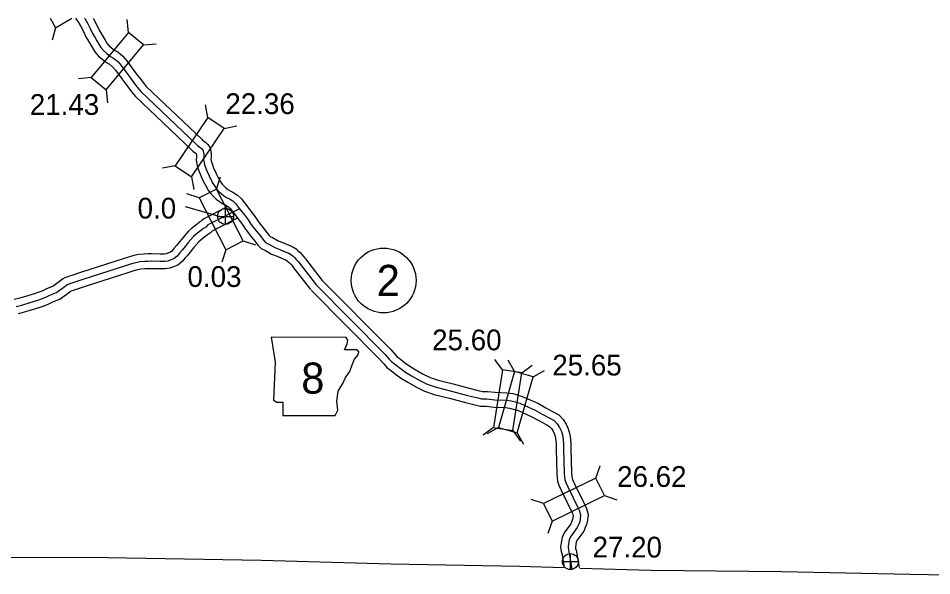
# Model space of a CAD drawing. Extents: x -83719 to 153526, y -11835 to 11446.
# Drawn here: x -4375 to -3756, y -4528 to -4150 of the extents above; entities that cross this region are included whole.
import ezdxf

# ---------------------------------------------------------------- set-up
doc = ezdxf.new("R2010")
doc.units = 0
for name, color, linetype in [('Level 10', 7, 'Continuous'), ('Level 2', 7, 'Continuous'), ('Level 20', 7, 'Continuous'), ('Level 21', 7, 'Continuous'), ('Level 25', 7, 'Continuous'), ('Level 26', 7, 'Continuous'), ('Level 27', 7, 'Continuous'), ('Level 58', 7, 'Continuous'), ('Level 59', 7, 'Continuous')]:
    doc.layers.add(name, color=color, linetype=linetype)

msp = doc.modelspace()

# ---------------------------------------------------------------- linework, layer by layer
at = {"layer": 'Level 10'}
for points in [[(-4336.57, -4149.53), (-4336.12, -4150.18), (-4334.58, -4152.45), (-4332.93, -4155.2), (-4331.25, -4158.56), (-4329.54, -4162.18), (-4327.88, -4164.97), (-4326.44, -4167.34), (-4325.07, -4169.56), (-4323.57, -4172.21), (-4321.25, -4174.97), (-4318.65, -4177.26), (-4315.71, -4179.58), (-4313.68, -4180.7), (-4311.48, -4182.52), (-4309.5, -4184.75), (-4305.1, -4190.67), (-4303.27, -4193.34), (-4301.01, -4196.33), (-4298.6, -4199.4), (-4295.95, -4202.63), (-4258.08, -4238.6), (-4257.12, -4239.64), (-4255.52, -4240.84), (-4254.71, -4241.39), (-4254.7, -4241.41), (-4254.66, -4241.56), (-4254.61, -4242.01), (-4254.63, -4243.43), (-4254.73, -4245.9), (-4254.29, -4248.37), (-4253.83, -4250.22), (-4252.94, -4253.02), (-4251.87, -4255.69), (-4250.82, -4257.92), (-4249.93, -4259.95), (-4249.1, -4261.54), (-4248.17, -4263.29), (-4246.57, -4266.09), (-4244.77, -4268.42), (-4242.85, -4270.66), (-4241.09, -4272.35), (-4239.02, -4273.8), (-4236.74, -4275.38), (-4234.66, -4276.39), (-4232.92, -4277.48), (-4231.72, -4278.6), (-4229.2, -4281.83)], [(-4324.67, -4149.53), (-4324.16, -4150.37), (-4322.25, -4154.2), (-4320.7, -4157.49), (-4319.31, -4159.82), (-4317.92, -4162.11), (-4316.46, -4164.47), (-4315.32, -4166.48), (-4314.07, -4167.96), (-4312.24, -4169.58), (-4310.15, -4171.23), (-4308.03, -4172.4), (-4304.52, -4175.29), (-4301.73, -4178.43), (-4296.96, -4184.86), (-4295.15, -4187.5), (-4293.1, -4190.22), (-4290.8, -4193.13), (-4288.61, -4195.8), (-4250.98, -4231.56), (-4250.4, -4232.18), (-4249.71, -4232.7), (-4248.21, -4233.71), (-4246.88, -4235.09), (-4246.18, -4236.16), (-4245.36, -4237.57), (-4244.78, -4239.81), (-4244.61, -4241.57), (-4244.63, -4243.69), (-4244.7, -4245.23), (-4244.51, -4246.29), (-4244.21, -4247.5), (-4243.53, -4249.63), (-4242.7, -4251.69), (-4241.71, -4253.78), (-4240.91, -4255.62), (-4240.24, -4256.89), (-4239.41, -4258.47), (-4238.24, -4260.52), (-4237.02, -4262.1), (-4235.57, -4263.78), (-4234.71, -4264.6), (-4233.29, -4265.6), (-4231.68, -4266.72), (-4229.82, -4267.62), (-4226.8, -4269.5), (-4224.31, -4271.83), (-4221.31, -4275.69)], [(-4233.37, -4277.3), (-4245.46, -4283.51), (-4249.63, -4285.66), (-4251.35, -4287.25), (-4252.72, -4288.2), (-4254.97, -4289.82), (-4257.9, -4292.27), (-4259.98, -4294.04), (-4263.91, -4298.56), (-4266.11, -4301.24), (-4268.13, -4303.73), (-4269.84, -4305.67), (-4271.31, -4307.45), (-4272.28, -4308.26), (-4275.15, -4309.39), (-4276.37, -4309.53), (-4279.2, -4309.49), (-4285.02, -4309.44), (-4287.53, -4309.46), (-4289.95, -4309.61), (-4293.8, -4309.72), (-4297.08, -4310.59), (-4300.05, -4311.36), (-4304.3, -4312.84), (-4333.22, -4322.03)], [(-4221.29, -4275.71), (-4218.29, -4279.6), (-4215.36, -4283.45), (-4213.45, -4286.27), (-4211.24, -4289.27), (-4209.99, -4290.85), (-4206.79, -4294.84), (-4205.23, -4296.9), (-4204.62, -4297.55), (-4203.03, -4298.31), (-4199.17, -4300.48), (-4195.99, -4301.78), (-4193.47, -4302.83), (-4189.7, -4304.41), (-4186.95, -4306.04), (-4185.65, -4307.23), (-4184.41, -4308.24), (-4183.15, -4309.72), (-4181.64, -4311.29), (-4180.58, -4312.8), (-4169.27, -4327.38)], [(-4229.21, -4281.82), (-4226.22, -4285.69), (-4223.49, -4289.28), (-4221.62, -4292.04), (-4219.19, -4295.34), (-4217.81, -4297.08), (-4214.68, -4300.99), (-4212.87, -4303.38), (-4210.6, -4305.78), (-4207.63, -4307.19), (-4203.53, -4309.5), (-4199.81, -4311.02), (-4197.33, -4312.06), (-4194.2, -4313.37), (-4192.94, -4314.11), (-4192.22, -4314.77), (-4191.44, -4315.41), (-4190.56, -4316.45), (-4189.38, -4317.67), (-4188.62, -4318.75), (-4177.17, -4333.51)], [(-4226.72, -4285.13), (-4240.89, -4292.4), (-4243.83, -4293.92), (-4245.08, -4295.08), (-4246.96, -4296.37), (-4248.82, -4297.72), (-4251.45, -4299.92), (-4252.94, -4301.18), (-4256.27, -4305.01), (-4258.36, -4307.56), (-4260.5, -4310.19), (-4262.23, -4312.15), (-4264.19, -4314.54), (-4267.13, -4316.97), (-4272.7, -4319.17), (-4275.87, -4319.54), (-4279.31, -4319.49), (-4285.02, -4319.44), (-4287.17, -4319.45), (-4289.49, -4319.6), (-4292.36, -4319.68), (-4294.54, -4320.26), (-4297.15, -4320.94), (-4301.14, -4322.33), (-4330.19, -4331.56)], [(-4348.47, -4328.66), (-4344.73, -4325.8)], [(-4333.27, -4322.05), (-4339.22, -4324), (-4340.64, -4324.42), (-4341.84, -4324.86), (-4342.69, -4325.21), (-4343.97, -4325.65), (-4345.38, -4326.46), (-4346.13, -4326.91)], [(-4169.67, -4326.92), (-4122.7, -4374.21), (-4119.89, -4377.49), (-4118.57, -4379.02), (-4116.14, -4380.8), (-4113.37, -4383.05), (-4109.84, -4385.54), (-4106.05, -4387.9), (-4100.64, -4390.99), (-4096.02, -4393.26), (-4090.51, -4395.1), (-4080.22, -4397.59), (-4069.44, -4400.53), (-4063.32, -4402.08), (-4060.41, -4402.68), (-4057.03, -4402.85), (-4051.84, -4403.32), (-4043.95, -4403.58), (-4039.83, -4404.22), (-4036.87, -4405.08), (-4033.41, -4406.07), (-4029.59, -4407.7), (-4022.5, -4411), (-4017.53, -4413.74), (-4012.38, -4416.47), (-4008.67, -4418.56), (-4005.75, -4421.73), (-4003.72, -4424.88), (-4002.23, -4428.16), (-4001.31, -4430.94), (-4000.76, -4434.84), (-4000.51, -4438.38), (-4000.42, -4441.83), (-3999.98, -4457.79), (-3999.72, -4460.58), (-3999.66, -4461.57), (-3999.32, -4462.55), (-3997.99, -4465.32), (-3990.77, -4480.07), (-3989.73, -4482.12), (-3989.38, -4483.71), (-3988.74, -4486.17), (-3989.2, -4489.97), (-3989.57, -4492.27), (-3990.47, -4494.65), (-3991.75, -4497.54), (-3996.37, -4503.82), (-3996.82, -4504.82), (-3997.16, -4506.85), (-3997.32, -4508.26), (-3997.22, -4509.31), (-3996.88, -4510.43), (-3994.88, -4522.08)], [(-4378.21, -4340.16), (-4374.43, -4339.27), (-4368.79, -4337.58), (-4363.72, -4336.01), (-4361.38, -4335.19), (-4358.69, -4334.17), (-4356.05, -4332.85), (-4352, -4331.22), (-4351.23, -4330.69), (-4348.4, -4328.6)], [(-4330.15, -4331.55), (-4336.25, -4333.55), (-4337.49, -4333.92), (-4338.24, -4334.2), (-4339.19, -4334.57), (-4339.78, -4334.78), (-4340.32, -4335.09), (-4341.01, -4335.5)], [(-4375.65, -4349.83), (-4371.85, -4348.94), (-4365.87, -4347.14), (-4360.59, -4345.51), (-4357.95, -4344.59), (-4354.67, -4343.33), (-4351.95, -4341.98), (-4347.25, -4340.09), (-4345.44, -4338.84), (-4342.46, -4336.66)], [(-4342.39, -4336.6), (-4340.53, -4335.18)], [(-4176.76, -4333.97), (-4130.06, -4380.99), (-4127.48, -4384), (-4125.4, -4386.41), (-4122.25, -4388.72), (-4119.42, -4391.02), (-4115.36, -4393.88), (-4111.17, -4396.49), (-4105.32, -4399.83), (-4099.82, -4402.53), (-4093.28, -4404.72), (-4082.71, -4407.28), (-4071.98, -4410.2), (-4065.57, -4411.82), (-4061.68, -4412.63), (-4057.73, -4412.82), (-4052.46, -4413.31), (-4044.88, -4413.56), (-4042, -4414), (-4039.64, -4414.69), (-4036.77, -4415.51), (-4033.66, -4416.84), (-4027.03, -4419.92), (-4022.28, -4422.54), (-4017.18, -4425.24), (-4014.96, -4426.5), (-4013.69, -4427.88), (-4012.52, -4429.68), (-4011.56, -4431.81), (-4011.09, -4433.23), (-4010.71, -4435.88), (-4010.5, -4438.88), (-4010.41, -4442.11), (-4009.97, -4458.38), (-4009.7, -4461.34), (-4009.56, -4463.55), (-4008.58, -4466.37), (-4006.98, -4469.69), (-3999.72, -4484.54), (-3999.23, -4485.5), (-3999.11, -4486.04), (-3998.9, -4486.86), (-3999.11, -4488.59), (-3999.28, -4489.69), (-3999.72, -4490.85), (-4000.45, -4492.49), (-4005.04, -4498.74), (-4006.46, -4501.87), (-4007.06, -4505.45), (-4007.37, -4508.17), (-4007.08, -4511.26), (-4006.63, -4512.75), (-4005.05, -4521.92)]]:
    msp.add_lwpolyline(points, dxfattribs=at)
at = {"layer": 'Level 2'}
for points in [[(-4957.4, -4504.13), (-4919.56, -4503.96), (-4917.36, -4504.16), (-4830.3, -4507.52), (-4737.87, -4511.88), (-4736.7, -4511.79), (-4650.39, -4514.4), (-4648.66, -4514.34), (-4566.66, -4516.43), (-4563.06, -4516.62), (-4473.92, -4516.38), (-4469.88, -4516.53), (-4385.62, -4515.36), (-4383.52, -4515.36), (-4328.12, -4515.28)], [(-4328.12, -4515.28), (-4210.3, -4517.28), (-4122.73, -4519.63), (-4035.26, -4521.38), (-4005.13, -4522.26)], [(-3994.43, -4522.57), (-3946.16, -4523.97), (-3857.42, -4524.92), (-3770.11, -4526.71), (-3708.13, -4527.77)]]:
    msp.add_lwpolyline(points, dxfattribs=at)
at = {"layer": 'Level 20'}
for p, q in [((-4300.75, -4159.22), (-4301.6, -4150.46)), ((-4350.22, -4155.91), (-4352.47, -4164.42)), ((-4290.57, -4167.61), (-4281.81, -4166.77)), ((-4325.93, -4189.79), (-4334.69, -4190.64)), ((-4315.74, -4198.18), (-4314.89, -4206.94)), ((-4246.77, -4216.82), (-4248.44, -4208.19)), ((-4235.83, -4224.21), (-4227.19, -4222.54)), ((-4268.94, -4249.64), (-4277.57, -4251.31)), ((-4258, -4257.03), (-4256.32, -4265.67)), ((-4241.02, -4265.41), (-4238.32, -4257.03)), ((-4252.76, -4271.43), (-4261.14, -4268.73)), ((-4222.94, -4300.64), (-4214.57, -4303.34)), ((-4234.69, -4306.67), (-4237.39, -4315.04)), ((-4046.79, -4388.16), (-4051.99, -4381.06)), ((-4038.68, -4389.16), (-4042.94, -4381.47)), ((-4033.75, -4390.19), (-4026.64, -4384.99)), ((-4025.99, -4392.81), (-4018.29, -4388.54)), ((-4052.86, -4427.3), (-4059.96, -4432.49)), ((-4049.61, -4427.22), (-4057.31, -4431.49)), ((-4039.82, -4429.32), (-4034.62, -4436.42)), ((-4036.92, -4430.87), (-4032.66, -4438.57)), ((-3983.4, -4461.47), (-3980.54, -4453.14)), ((-4018.97, -4478.87), (-4027.29, -4476.02)), ((-3977.59, -4473.32), (-3969.27, -4476.18)), ((-4013.16, -4490.73), (-4016.02, -4499.05))]:
    msp.add_line(p, q, dxfattribs=at)
msp.add_lwpolyline([(-4353.93, -4149.53), (-4350.22, -4155.91), (-4339.24, -4149.53)], dxfattribs=at)
for points in [[(-4315.74, -4198.18), (-4290.57, -4167.61), (-4300.75, -4159.22), (-4325.93, -4189.79)], [(-4258, -4257.03), (-4235.83, -4224.21), (-4246.77, -4216.82), (-4268.94, -4249.64)], [(-4222.94, -4300.64), (-4241.02, -4265.41), (-4252.76, -4271.43), (-4234.69, -4306.67)], [(-4039.82, -4429.32), (-4033.75, -4390.19), (-4046.79, -4388.16), (-4052.86, -4427.3)], [(-4038.68, -4389.16), (-4049.61, -4427.22), (-4036.92, -4430.87), (-4025.99, -4392.81)], [(-3983.4, -4461.47), (-4018.97, -4478.87), (-4013.16, -4490.73), (-3977.59, -4473.32)]]:
    msp.add_lwpolyline(points, close=True, dxfattribs=at)
at = {"layer": 'Level 21'}
msp.add_lwpolyline([(-4203.77, -4365.99), (-4201.23, -4382.91), (-4202.36, -4408.57), (-4200.11, -4409.98), (-4195.88, -4409.98), (-4195.88, -4419), (-4160.35, -4419), (-4158.66, -4415.33), (-4159.22, -4409.41), (-4158.37, -4402.65), (-4155.27, -4397.29), (-4153.3, -4393.34), (-4150.48, -4389.11), (-4148.79, -4384.6), (-4147.38, -4380.93), (-4144.84, -4377.83), (-4144.28, -4375.86), (-4145.4, -4374.45), (-4154.15, -4374.45), (-4152.17, -4370.5), (-4151.89, -4367.96), (-4153.06, -4366.02)], close=True, dxfattribs=at)
at = {"layer": 'Level 25'}
msp.add_line((-4262.26, -4277.26), (-4235.98, -4284.71), dxfattribs=at)
at = {"layer": 'Level 26'}
for p, q in [((-4240.25, -4283.93), (-4229.41, -4283.93)), ((-4234.83, -4289.35), (-4234.83, -4278.52)), ((-4000.78, -4523.63), (-4000.78, -4512.79)), ((-4006.19, -4518.21), (-3995.36, -4518.21))]:
    msp.add_line(p, q, dxfattribs=at)
for centre in [(-4234.83, -4283.93), (-4000.78, -4518.21)]:
    msp.add_circle(centre, 5.42, dxfattribs=at)
at = {"layer": 'Level 27'}
msp.add_circle((-4127.51, -4327.41), 22, dxfattribs=at)
at = {"layer": 'Level 59'}
for points in [[(-4330.52, -4149.53), (-4330.37, -4149.76), (-4328.54, -4152.78), (-4326.75, -4156.38), (-4325.12, -4159.84), (-4323.6, -4162.4), (-4322.18, -4164.72), (-4320.76, -4167.02), (-4319.44, -4169.34), (-4317.66, -4171.47), (-4315.45, -4173.42), (-4312.93, -4175.4), (-4310.85, -4176.55), (-4308, -4178.9), (-4305.62, -4181.59), (-4301.03, -4187.76), (-4299.21, -4190.42), (-4297.06, -4193.28), (-4294.7, -4196.26), (-4292.28, -4199.22), (-4254.53, -4235.08), (-4253.76, -4235.91), (-4252.62, -4236.77), (-4251.44, -4237.56), (-4250.81, -4238.22), (-4250.43, -4238.79), (-4250.03, -4239.49), (-4249.72, -4240.69), (-4249.61, -4241.79), (-4249.63, -4243.56), (-4249.71, -4245.56), (-4249.4, -4247.33), (-4249.02, -4248.86), (-4248.23, -4251.33), (-4247.28, -4253.69), (-4246.27, -4255.85), (-4245.42, -4257.78), (-4244.67, -4259.21), (-4243.79, -4260.88), (-4242.41, -4263.3), (-4240.89, -4265.26), (-4239.21, -4267.22), (-4237.9, -4268.48), (-4236.16, -4269.7), (-4234.21, -4271.05), (-4232.24, -4272.01), (-4229.86, -4273.49), (-4228.01, -4275.21), (-4225.25, -4278.76)], [(-4225.25, -4278.76), (-4243.17, -4287.96), (-4246.73, -4289.79), (-4248.21, -4291.17), (-4249.84, -4292.28), (-4251.89, -4293.77), (-4254.67, -4296.09), (-4256.46, -4297.61), (-4260.09, -4301.78), (-4262.24, -4304.4), (-4264.32, -4306.96), (-4266.03, -4308.91), (-4267.75, -4310.99), (-4269.7, -4312.61), (-4273.92, -4314.28), (-4276.12, -4314.53), (-4279.25, -4314.49), (-4285.02, -4314.44), (-4287.35, -4314.46), (-4289.72, -4314.61), (-4293.08, -4314.7), (-4295.81, -4315.42), (-4298.6, -4316.15), (-4302.72, -4317.58), (-4331.71, -4326.8)], [(-4225.25, -4278.76), (-4222.26, -4282.65), (-4219.43, -4286.36), (-4217.54, -4289.15), (-4215.21, -4292.31), (-4213.9, -4293.97), (-4210.74, -4297.92), (-4209.05, -4300.14), (-4207.61, -4301.66), (-4205.33, -4302.75), (-4201.35, -4304.99), (-4197.9, -4306.4), (-4195.4, -4307.44), (-4191.95, -4308.89), (-4189.94, -4310.07), (-4188.94, -4311), (-4187.93, -4311.83), (-4186.85, -4313.09), (-4185.51, -4314.48), (-4184.6, -4315.77), (-4173.22, -4330.44)], [(-4331.71, -4326.8), (-4337.73, -4328.78), (-4339.07, -4329.17), (-4340.04, -4329.53), (-4340.94, -4329.89), (-4341.88, -4330.22), (-4342.85, -4330.78), (-4343.57, -4331.21)], [(-4376.93, -4344.99), (-4373.14, -4344.11), (-4367.33, -4342.36), (-4362.15, -4340.76), (-4359.67, -4339.89), (-4356.68, -4338.75), (-4354, -4337.41), (-4349.62, -4335.65), (-4348.33, -4334.77), (-4345.43, -4332.63)], [(-4345.43, -4332.63), (-4343.57, -4331.21)], [(-4173.22, -4330.44), (-4126.38, -4377.6), (-4123.69, -4380.74), (-4121.99, -4382.72), (-4119.19, -4384.76), (-4116.4, -4387.03), (-4112.6, -4389.71), (-4108.61, -4392.19), (-4102.98, -4395.41), (-4097.92, -4397.89), (-4091.89, -4399.91), (-4081.46, -4402.44), (-4070.71, -4405.37), (-4064.44, -4406.95), (-4061.04, -4407.66), (-4057.38, -4407.84), (-4052.15, -4408.32), (-4044.42, -4408.57), (-4040.92, -4409.11), (-4038.26, -4409.88), (-4035.09, -4410.79), (-4031.63, -4412.27), (-4024.77, -4415.46), (-4019.91, -4418.14), (-4014.78, -4420.85), (-4011.82, -4422.53), (-4009.72, -4424.8), (-4008.12, -4427.28), (-4006.9, -4429.98), (-4006.2, -4432.09), (-4005.74, -4435.36), (-4005.51, -4438.63), (-4005.41, -4441.97), (-4004.97, -4458.09), (-4004.71, -4460.96), (-4004.61, -4462.56), (-4003.95, -4464.46), (-4002.49, -4467.5), (-3995.24, -4482.3), (-3994.48, -4483.81), (-3994.25, -4484.88), (-3993.82, -4486.51), (-3994.15, -4489.28), (-3994.42, -4490.98), (-3995.09, -4492.75), (-3996.1, -4495.02), (-4000.7, -4501.28), (-4001.64, -4503.34), (-4002.11, -4506.15), (-4002.35, -4508.22), (-4002.15, -4510.28), (-4001.75, -4511.59), (-3999.78, -4523.04)]]:
    msp.add_lwpolyline(points, dxfattribs=at)

# ---------------------------------------------------------------- texts
at = {"layer": 'Level 21'}
msp.add_text('8', height=21.12, dxfattribs=at).set_placement((-4183.43, -4404.26))
at = {"layer": 'Level 25'}
for s, p in [('0.0', (-4294.51, -4285.4)), ('27.20', (-3985.73, -4515.4))]:
    msp.add_text(s, height=14.08, dxfattribs=at).set_placement(p)
at = {"layer": 'Level 27'}
msp.add_text('2', height=21.12, dxfattribs=at).set_placement((-4132.23, -4337.97))
at = {"layer": 'Level 58'}
for s, p in [('21.43', (-4367.67, -4215.08)), ('22.36', (-4234.95, -4214.52)), ('0.03', (-4260.64, -4331.82)), ('25.60', (-4094.6, -4374.82)), ('25.65', (-4013.06, -4391.9)), ('26.62', (-3969.06, -4467.49))]:
    msp.add_text(s, height=14.08, dxfattribs=at).set_placement(p)

doc.saveas('drawing.dxf')
